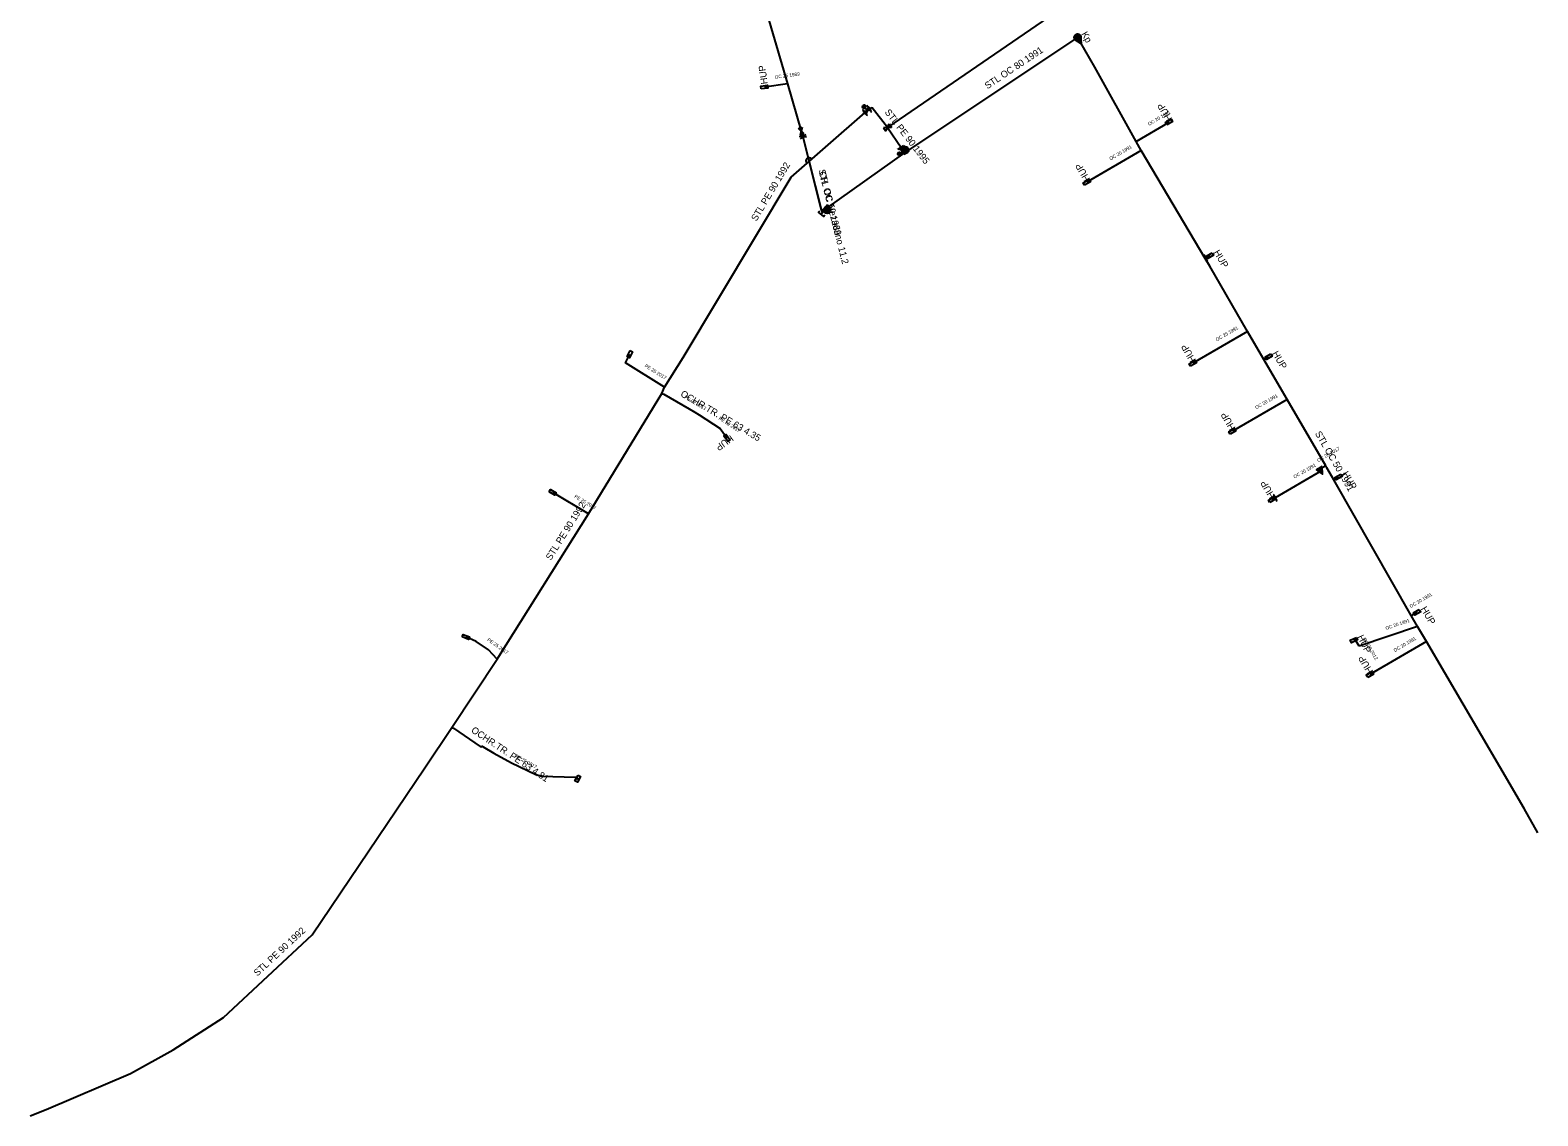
# Model space of a CAD drawing. Extents: x -734239 to -733693, y -1053757 to -1053379.
# Drawn here: x -734167.4 to -733944.2, y -1053757.2 to -1053596.5 of the extents above; entities that cross this region are included whole.
import ezdxf

# ---------------------------------------------------------------- set-up
doc = ezdxf.new("R2010")
doc.units = 0
for name, color, linetype in [('ST Kapák - provoz_popis', 7, 'Continuous'), ('ST Ochoz plynovodu - provoz', 7, 'Continuous'), ('ST OP Chráni_ka - provoz', 7, 'Continuous'), ('ST Úsek p_ípojky - provoz', 7, 'Continuous'), ('ST Úsek p_ípojky - provoz - priblizny prubeh', 7, 'Continuous'), ('ST Úsek plynovodu - provoz', 7, 'Continuous'), ('ST_HUP_22_23_popis', 7, 'Continuous'), ('Vrstva 1', 7, 'Continuous')]:
    doc.layers.add(name, color=color, linetype=linetype)

msp = doc.modelspace()

# ---------------------------------------------------------------- linework, layer by layer
at = {"layer": 'ST Ochoz plynovodu - provoz'}
for points in [[(-734038.21, -1053614.26), (-734037.95, -1053614.08), (-734037.85, -1053614.29), (-734037.65, -1053614.47)], [(-734049.48, -1053622.88), (-734049.33, -1053623.03), (-734049.42, -1053623.17), (-734049.54, -1053623.28), (-734049.71, -1053623.1)]]:
    msp.add_lwpolyline(points, dxfattribs=at)
at = {"layer": 'ST OP Chráni_ka - provoz'}
for points in [[(-734050.22, -1053623.25), (-734052.98, -1053612.39)], [(-734073.59, -1053650.41), (-734069.84, -1053652.61)], [(-734069, -1053653.1), (-734068.33, -1053653.48)], [(-734104.73, -1053699.88), (-734100.74, -1053702.56)], [(-734100.34, -1053702.63), (-734098.72, -1053703.58)], [(-734096.13, -1053705.02), (-734092.52, -1053706.71)], [(-734091.65, -1053706.97), (-734086.72, -1053707.11)]]:
    msp.add_lwpolyline(points, dxfattribs=at)
at = {"layer": 'ST Úsek p_ípojky - provoz'}
for points in [[(-734055.28, -1053604.51), (-734058.7, -1053604.98)], [(-734002.95, -1053614.35), (-734010.96, -1053619.06)], [(-733993.35, -1053630.29), (-733992.74, -1053629.93)], [(-733993.44, -1053630.35), (-733993.35, -1053630.29)], [(-733987.17, -1053641.14), (-733995.29, -1053645.84)], [(-734073.5, -1053649.41), (-734079.25, -1053645.8), (-734078.62, -1053644.5)], [(-733984.76, -1053645.29), (-733984.07, -1053644.89)], [(-734073.9, -1053650.31), (-734073.59, -1053650.41), (-734069.84, -1053652.61), (-734069, -1053653.1), (-734068.33, -1053653.48)], [(-733981.33, -1053651.21), (-733989.43, -1053655.91)], [(-734068.33, -1053653.48), (-734065.26, -1053655.49), (-734064.23, -1053656.92)], [(-733975.62, -1053661.03), (-733976.49, -1053661.53), (-733976.32, -1053661.83)], [(-733976.32, -1053661.83), (-733983.11, -1053665.77)], [(-733974.42, -1053663.1), (-733973.73, -1053662.7)], [(-734084.75, -1053668.12), (-734090.03, -1053664.97)], [(-733983.11, -1053665.77), (-733983.55, -1053666.02)], [(-733962.96, -1053683.21), (-733962.09, -1053682.71)], [(-733962.02, -1053684.82), (-733970.68, -1053687.71)], [(-734098.24, -1053689.67), (-734099.55, -1053688.27), (-734101.34, -1053687.02), (-734102.88, -1053686.36)], [(-733970.68, -1053687.71), (-733971.25, -1053686.74), (-733971.45, -1053686.83)], [(-733960.72, -1053687.04), (-733969.07, -1053691.93)], [(-734104.95, -1053699.77), (-734104.73, -1053699.88), (-734100.74, -1053702.56), (-734100.54, -1053702.65), (-734100.49, -1053702.55), (-734100.34, -1053702.63), (-734098.72, -1053703.58), (-734096.13, -1053705.02), (-734092.52, -1053706.71), (-734091.65, -1053706.97), (-734086.72, -1053707.11), (-734086.31, -1053707.34)]]:
    msp.add_lwpolyline(points, dxfattribs=at)
at = {"layer": 'ST Úsek p_ípojky - provoz - priblizny prubeh'}
msp.add_lwpolyline([(-734003.69, -1053613.01), (-733998.81, -1053610.14)], dxfattribs=at)
at = {"layer": 'ST Úsek plynovodu - provoz'}
for points in [[(-734066.74, -1053498.42), (-734070.16, -1053518.19), (-734070.63, -1053521.47), (-734070.96, -1053536.4), (-734070.88, -1053545.79), (-734069.71, -1053552.02), (-734065.01, -1053571.09), (-734063.82, -1053575.62), (-734059.57, -1053589.99), (-734059.12, -1053591.3), (-734055.28, -1053604.51), (-734053.25, -1053611.48)], [(-733992.91, -1053579.78), (-733994.62, -1053581), (-734014.15, -1053594.44), (-734015.86, -1053594.09), (-734040.47, -1053610.96)], [(-734012.33, -1053597.61), (-734037.92, -1053614.67)], [(-734012.02, -1053598.15), (-734012.33, -1053597.61)], [(-733944.22, -1053715.38), (-733946.26, -1053711.75), (-733949.86, -1053705.6), (-733960.72, -1053687.04), (-733962.02, -1053684.82), (-733962.96, -1053683.21), (-733974.42, -1053663.1), (-733975.45, -1053661.32), (-733975.62, -1053661.03), (-733981.33, -1053651.21), (-733984.76, -1053645.29), (-733987.17, -1053641.14), (-733992.78, -1053631.46), (-733993.44, -1053630.35), (-734002.95, -1053614.35), (-734003.69, -1053613.01), (-734009.77, -1053602.02), (-734012.02, -1053598.15)], [(-734070.74, -1053645.02), (-734054.75, -1053618.31), (-734043.79, -1053608.73)], [(-734043.79, -1053608.73), (-734043.48, -1053608.46)], [(-734043.15, -1053608.21), (-734043.48, -1053608.46)], [(-734040.47, -1053610.96), (-734042.74, -1053608.03), (-734043.15, -1053608.21)], [(-734053.25, -1053611.48), (-734053, -1053612.32), (-734050.22, -1053623.25), (-734050.14, -1053623.61)], [(-734040.47, -1053610.96), (-734038.47, -1053613.9)], [(-734038.47, -1053613.9), (-734038.21, -1053614.26), (-734038.11, -1053614.39)], [(-734038.11, -1053614.39), (-734037.92, -1053614.67)], [(-734037.92, -1053614.67), (-734049.48, -1053622.88), (-734049.59, -1053622.98)], [(-734049.59, -1053622.98), (-734049.71, -1053623.1), (-734050.14, -1053623.61)], [(-734050.14, -1053623.61), (-734050.3, -1053623.79)], [(-734108.93, -1053705.75), (-734104.95, -1053699.77), (-734098.24, -1053689.67), (-734097.98, -1053689.28), (-734084.75, -1053668.12), (-734073.9, -1053650.31), (-734073.5, -1053649.41), (-734070.74, -1053645.02)], [(-734167.37, -1053757.25), (-734164.99, -1053756.32), (-734152.5, -1053750.98), (-734146.2, -1053747.48), (-734138.77, -1053742.67), (-734125.62, -1053730.47), (-734108.93, -1053705.75)]]:
    msp.add_lwpolyline(points, dxfattribs=at)
at = {"layer": 'Vrstva 1'}
for p, q in [((-734044.12, -1053608.36), (-734044.01, -1053608.26)), ((-734044.12, -1053608.36), (-734043.46, -1053609.11)), ((-734044.06, -1053608.57), (-734042.91, -1053608.35)), ((-734043.66, -1053609.02), (-734044.06, -1053608.57)), ((-734043.49, -1053608.46), (-734043.79, -1053608.07)), ((-734043.31, -1053607.91), (-734043.66, -1053609.02)), ((-734043.46, -1053609.11), (-734043.57, -1053609.21)), ((-734043.46, -1053607.81), (-734043.34, -1053607.72)), ((-734042.85, -1053608.61), (-734043.46, -1053607.81)), ((-734042.91, -1053608.35), (-734043.31, -1053607.91)), ((-734042.85, -1053608.61), (-734042.97, -1053608.7)), ((-734053.67, -1053611.08), (-734053.1, -1053610.92)), ((-734052.82, -1053611.88), (-734053.67, -1053611.08)), ((-734052.58, -1053611.99), (-734053.42, -1053612.65)), ((-734053.1, -1053610.92), (-734053.39, -1053612.04)), ((-734053.39, -1053612.04), (-734052.82, -1053611.88)), ((-734039.89, -1053610.93), (-734041.05, -1053611)), ((-734041.05, -1053611), (-734040.71, -1053611.49)), ((-734040.71, -1053611.49), (-734040.23, -1053610.43)), ((-734040.23, -1053610.43), (-734039.89, -1053610.93)), ((-734052.46, -1053612.37), (-734053.54, -1053612.27)), ((-734038.88, -1053614.18), (-734038.97, -1053614.06)), ((-734038.88, -1053614.18), (-734038.06, -1053613.62)), ((-734038.15, -1053613.81), (-734038.64, -1053614.16)), ((-734038.64, -1053614.16), (-734037.58, -1053614.63)), ((-734038.11, -1053614.39), (-734038.52, -1053614.69)), ((-734037.47, -1053614.43), (-734038.22, -1053614.15)), ((-734038.07, -1053614.97), (-734038.15, -1053613.81)), ((-734038.06, -1053613.62), (-734037.97, -1053613.74)), ((-734037.71, -1053613.91), (-734037.98, -1053614.67)), ((-734037.58, -1053614.63), (-734038.07, -1053614.97)), ((-734050.16, -1053623.12), (-734049.02, -1053622.85)), ((-734049.74, -1053623.55), (-734050.16, -1053623.12)), ((-734049.02, -1053623.17), (-734049.82, -1053623.17)), ((-734049.44, -1053622.42), (-734049.74, -1053623.55)), ((-734049.02, -1053622.85), (-734049.44, -1053622.42)), ((-734049.42, -1053622.77), (-734049.42, -1053623.57)), ((-733993.61, -1053629.86), (-733993.48, -1053629.79)), ((-733993.1, -1053630.73), (-733993.61, -1053629.86)), ((-733993.1, -1053630.73), (-733993.23, -1053630.8)), ((-733983.36, -1053665.34), (-733983.24, -1053665.26)), ((-733983.36, -1053665.34), (-733982.86, -1053666.2)), ((-733982.86, -1053666.2), (-733982.99, -1053666.28))]:
    msp.add_line(p, q, dxfattribs=at)
for points in [[(-734011.91, -1053597.34), (-734011.89, -1053597.38), (-734011.87, -1053597.43), (-734011.85, -1053597.47), (-734011.84, -1053597.52), (-734011.84, -1053597.57), (-734011.83, -1053597.62), (-734011.84, -1053597.67), (-734011.84, -1053597.72), (-734011.86, -1053597.77), (-734011.87, -1053597.81), (-734011.9, -1053597.86), (-734011.92, -1053597.9), (-734011.95, -1053597.94), (-734011.99, -1053597.97), (-734012.02, -1053598), (-734012.06, -1053598.03), (-734012.11, -1053598.06), (-734012.15, -1053598.08), (-734012.2, -1053598.09), (-734012.24, -1053598.1), (-734012.29, -1053598.11), (-734012.34, -1053598.11), (-734012.39, -1053598.11), (-734012.44, -1053598.1), (-734012.49, -1053598.09), (-734012.53, -1053598.07), (-734012.58, -1053598.05), (-734012.62, -1053598.02), (-734012.66, -1053597.99), (-734012.69, -1053597.96), (-734012.73, -1053597.92), (-734012.76, -1053597.88), (-734012.78, -1053597.84), (-734012.8, -1053597.8), (-734012.82, -1053597.75), (-734012.83, -1053597.7), (-734012.83, -1053597.65), (-734012.83, -1053597.6), (-734012.83, -1053597.55), (-734012.82, -1053597.51), (-734012.81, -1053597.46), (-734012.79, -1053597.41), (-734012.77, -1053597.37), (-734012.75, -1053597.33), (-734012.72, -1053597.29), (-734012.68, -1053597.25), (-734012.65, -1053597.22), (-734012.61, -1053597.19), (-734012.56, -1053597.17), (-734012.52, -1053597.15), (-734012.47, -1053597.13), (-734012.42, -1053597.12), (-734012.38, -1053597.11), (-734012.33, -1053597.11), (-734012.28, -1053597.11), (-734012.23, -1053597.12), (-734012.18, -1053597.14), (-734012.13, -1053597.15), (-734012.09, -1053597.17), (-734012.05, -1053597.2), (-734012.01, -1053597.23), (-734011.97, -1053597.26), (-734011.94, -1053597.3)], [(-734011.84, -1053597.46), (-734012.7, -1053597.97), (-734011.77, -1053598.58)], [(-734012.52, -1053597.32), (-734012.49, -1053597.3), (-734012.46, -1053597.29), (-734012.43, -1053597.28), (-734012.4, -1053597.27), (-734012.36, -1053597.26), (-734012.33, -1053597.26), (-734012.29, -1053597.26), (-734012.26, -1053597.27), (-734012.23, -1053597.28), (-734012.19, -1053597.29), (-734012.16, -1053597.31), (-734012.13, -1053597.32), (-734012.11, -1053597.34), (-734012.08, -1053597.37), (-734012.06, -1053597.39), (-734012.04, -1053597.42), (-734012.02, -1053597.45), (-734012.01, -1053597.48), (-734012, -1053597.52), (-734011.99, -1053597.55), (-734011.98, -1053597.58), (-734011.98, -1053597.62), (-734011.99, -1053597.65), (-734011.99, -1053597.69), (-734012, -1053597.72), (-734012.01, -1053597.75), (-734012.03, -1053597.78), (-734012.05, -1053597.81), (-734012.07, -1053597.84), (-734012.09, -1053597.86), (-734012.12, -1053597.89), (-734012.14, -1053597.91), (-734012.17, -1053597.92), (-734012.21, -1053597.94), (-734012.24, -1053597.95), (-734012.27, -1053597.96), (-734012.31, -1053597.96), (-734012.34, -1053597.96), (-734012.37, -1053597.96), (-734012.41, -1053597.95), (-734012.44, -1053597.95), (-734012.47, -1053597.93), (-734012.5, -1053597.92), (-734012.53, -1053597.9), (-734012.56, -1053597.88), (-734012.59, -1053597.86), (-734012.61, -1053597.83), (-734012.63, -1053597.8), (-734012.65, -1053597.77), (-734012.66, -1053597.74), (-734012.67, -1053597.71), (-734012.68, -1053597.67), (-734012.68, -1053597.64), (-734012.68, -1053597.61), (-734012.68, -1053597.57), (-734012.68, -1053597.54), (-734012.67, -1053597.5), (-734012.66, -1053597.47), (-734012.64, -1053597.44), (-734012.62, -1053597.41), (-734012.6, -1053597.39), (-734012.58, -1053597.36), (-734012.55, -1053597.34)], [(-734012.17, -1053597.86), (-734012.2, -1053597.88), (-734012.22, -1053597.89), (-734012.25, -1053597.9), (-734012.28, -1053597.91), (-734012.31, -1053597.91), (-734012.34, -1053597.91), (-734012.37, -1053597.91), (-734012.4, -1053597.91), (-734012.43, -1053597.9), (-734012.45, -1053597.89), (-734012.48, -1053597.87), (-734012.51, -1053597.86), (-734012.53, -1053597.84), (-734012.55, -1053597.82), (-734012.57, -1053597.8), (-734012.59, -1053597.77), (-734012.6, -1053597.75), (-734012.61, -1053597.72), (-734012.62, -1053597.69), (-734012.63, -1053597.67), (-734012.63, -1053597.64), (-734012.63, -1053597.61), (-734012.63, -1053597.58), (-734012.63, -1053597.55), (-734012.62, -1053597.52), (-734012.61, -1053597.49), (-734012.6, -1053597.47), (-734012.58, -1053597.44), (-734012.56, -1053597.42), (-734012.54, -1053597.4), (-734012.52, -1053597.38), (-734012.5, -1053597.36), (-734012.47, -1053597.34), (-734012.44, -1053597.33), (-734012.42, -1053597.32), (-734012.39, -1053597.32), (-734012.36, -1053597.31), (-734012.33, -1053597.31), (-734012.3, -1053597.31), (-734012.27, -1053597.32), (-734012.24, -1053597.33), (-734012.21, -1053597.34), (-734012.19, -1053597.35), (-734012.16, -1053597.36), (-734012.14, -1053597.38), (-734012.12, -1053597.4), (-734012.1, -1053597.43), (-734012.08, -1053597.45), (-734012.07, -1053597.47), (-734012.05, -1053597.5), (-734012.05, -1053597.53), (-734012.04, -1053597.56), (-734012.03, -1053597.59), (-734012.03, -1053597.62), (-734012.04, -1053597.65), (-734012.04, -1053597.68), (-734012.05, -1053597.7), (-734012.06, -1053597.73), (-734012.07, -1053597.76), (-734012.09, -1053597.78), (-734012.11, -1053597.81), (-734012.13, -1053597.83), (-734012.15, -1053597.85)], [(-734012.51, -1053597.97), (-734011.88, -1053598.39), (-734011.93, -1053597.63)], [(-734012.25, -1053597.74), (-734012.27, -1053597.75), (-734012.28, -1053597.75), (-734012.29, -1053597.76), (-734012.31, -1053597.76), (-734012.32, -1053597.76), (-734012.34, -1053597.76), (-734012.35, -1053597.76), (-734012.37, -1053597.76), (-734012.38, -1053597.75), (-734012.39, -1053597.75), (-734012.41, -1053597.74), (-734012.42, -1053597.74), (-734012.43, -1053597.73), (-734012.44, -1053597.72), (-734012.45, -1053597.71), (-734012.46, -1053597.69), (-734012.47, -1053597.68), (-734012.47, -1053597.67), (-734012.48, -1053597.65), (-734012.48, -1053597.64), (-734012.48, -1053597.62), (-734012.48, -1053597.61), (-734012.48, -1053597.59), (-734012.48, -1053597.58), (-734012.48, -1053597.57), (-734012.47, -1053597.55), (-734012.47, -1053597.54), (-734012.46, -1053597.53), (-734012.45, -1053597.51), (-734012.44, -1053597.5), (-734012.43, -1053597.49), (-734012.42, -1053597.49), (-734012.4, -1053597.48), (-734012.39, -1053597.47), (-734012.38, -1053597.47), (-734012.36, -1053597.46), (-734012.35, -1053597.46), (-734012.33, -1053597.46), (-734012.32, -1053597.46), (-734012.3, -1053597.46), (-734012.29, -1053597.47), (-734012.27, -1053597.47), (-734012.26, -1053597.48), (-734012.25, -1053597.49), (-734012.24, -1053597.5), (-734012.23, -1053597.51), (-734012.22, -1053597.52), (-734012.21, -1053597.53), (-734012.2, -1053597.54), (-734012.19, -1053597.56), (-734012.19, -1053597.57), (-734012.19, -1053597.58), (-734012.18, -1053597.6), (-734012.18, -1053597.61), (-734012.18, -1053597.63), (-734012.19, -1053597.64), (-734012.19, -1053597.66), (-734012.2, -1053597.67), (-734012.2, -1053597.69), (-734012.21, -1053597.7), (-734012.22, -1053597.71), (-734012.23, -1053597.72), (-734012.24, -1053597.73)], [(-734011.99, -1053598.19), (-734012.02, -1053597.8), (-734012.32, -1053597.98)], [(-734059.17, -1053605.25), (-734059.22, -1053604.85), (-734058.23, -1053604.71), (-734058.18, -1053605.11)], [(-733999.14, -1053610.57), (-733999.34, -1053610.22), (-733998.48, -1053609.71), (-733998.28, -1053610.06)], [(-734011.3, -1053619.48), (-734011.5, -1053619.13), (-734010.63, -1053618.63), (-734010.43, -1053618.98)], [(-733992.41, -1053629.5), (-733992.21, -1053629.85), (-733993.07, -1053630.36), (-733993.27, -1053630.01)], [(-734078.58, -1053643.96), (-734078.22, -1053644.14), (-734078.66, -1053645.04), (-734079.02, -1053644.86)], [(-733995.62, -1053646.27), (-733995.82, -1053645.92), (-733994.96, -1053645.42), (-733994.76, -1053645.77)], [(-733983.73, -1053644.46), (-733983.53, -1053644.81), (-733984.4, -1053645.31), (-733984.6, -1053644.97)], [(-734063.78, -1053657.21), (-734064.1, -1053657.44), (-734064.68, -1053656.63), (-734064.36, -1053656.4)], [(-733989.76, -1053656.33), (-733989.96, -1053655.99), (-733989.1, -1053655.49), (-733988.9, -1053655.83)], [(-733976.14, -1053661.14), (-733977, -1053661.65), (-733976.07, -1053662.26)], [(-733976.81, -1053661.65), (-733976.18, -1053662.07), (-733976.23, -1053661.31)], [(-733976.29, -1053661.87), (-733976.32, -1053661.48), (-733976.62, -1053661.66)], [(-733973.4, -1053662.27), (-733973.2, -1053662.62), (-733974.06, -1053663.13), (-733974.26, -1053662.78)], [(-734090.56, -1053664.89), (-734090.36, -1053664.54), (-734089.5, -1053665.05), (-734089.7, -1053665.4)], [(-733983.88, -1053666.45), (-733984.08, -1053666.1), (-733983.21, -1053665.6), (-733983.01, -1053665.94)], [(-733961.76, -1053682.29), (-733961.56, -1053682.63), (-733962.42, -1053683.14), (-733962.62, -1053682.79)], [(-734103.42, -1053686.35), (-734103.26, -1053685.98), (-734102.34, -1053686.37), (-734102.5, -1053686.74)], [(-733971.08, -1053686.43), (-733970.91, -1053686.8), (-733971.81, -1053687.23), (-733971.99, -1053686.86)], [(-733969.4, -1053692.35), (-733969.61, -1053692.01), (-733968.74, -1053691.5), (-733968.54, -1053691.85)], [(-734086.24, -1053706.81), (-734085.89, -1053707), (-734086.38, -1053707.87), (-734086.73, -1053707.68)]]:
    msp.add_lwpolyline(points, close=True, dxfattribs=at)
msp.add_lwpolyline([(-734049.76, -1053623.93), (-734049.92, -1053624.12), (-734050.68, -1053623.47), (-734050.51, -1053623.28)], dxfattribs=at)
for centre, radius in [((-734043.95, -1053607.87), 0.249), ((-734044.03, -1053607.95), 0.0614), ((-734043.86, -1053607.82), 0.0614), ((-734037.85, -1053614.29), 0.5), ((-734037.85, -1053614.29), 0.4), ((-734038.72, -1053614.83), 0.249), ((-734038.77, -1053614.74), 0.0614), ((-734038.65, -1053614.91), 0.0614), ((-734049.42, -1053623.17), 0.5), ((-734049.42, -1053623.17), 0.4)]:
    msp.add_circle(centre, radius, dxfattribs=at)
msp.add_arc((-734052.04, -1053615.94), 0.5, 41, 221, dxfattribs=at)

# ---------------------------------------------------------------- texts
at = {"layer": 'ST Kapák - provoz_popis'}
msp.add_text('Kp', height=1, rotation=300, dxfattribs=at).set_placement((-734011.83, -1053597.11))
at = {"layer": 'ST OP Chráni_ka - provoz'}
for s, rotation, p in [('CH. OC Nezadáno 11,2', 284.2608, (-734050.63, -1053617.58)), ('OCHR.TR. PE 63 4.35', 329.6013, (-734071.21, -1053650.65)), ('OCHR.TR. PE 63 4.81', 326.1116, (-734102.18, -1053700.39))]:
    msp.add_text(s, height=1, rotation=rotation, dxfattribs=at).set_placement(p)
at = {"layer": 'ST Úsek p_ípojky - provoz'}
for s, rotation, p in [('OC 25 1989', 7.8085, (-734057.13, -1053603.75)), ('OC 20 1991', 30.429, (-734007.46, -1053615.84)), ('OC 25 1991', 30.0983, (-733991.73, -1053642.62)), ('PE 25 2017', 327.8783, (-734076.46, -1053646.37)), ('PE 32 2017', 329.6013, (-734070.6, -1053651.01)), ('OC 20 1991', 30.1218, (-733985.88, -1053652.69)), ('PE 32 2017', 326.7863, (-734065.51, -1053654.13)), ('OC 25 2017', 30.2069, (-733976.71, -1053660.5)), ('OC 20 1991', 30.1221, (-733980.22, -1053662.93)), ('PE 25 2017', 329.1801, (-734086.88, -1053665.69)), ('OC 20 1991', 30.1988, (-733963.03, -1053682.1)), ('OC 20 1991', 18.4627, (-733966.67, -1053685.32)), ('PE 25 2017', 325.0725, (-734099.77, -1053686.89)), ('OC 20 2012', 300.3294, (-733970.16, -1053686.62)), ('OC 20 1991', 30.337, (-733965.4, -1053688.62)), ('PE 25 2017', 330.9266, (-734095.69, -1053704.12))]:
    msp.add_text(s, height=0.5, rotation=rotation, dxfattribs=at).set_placement(p)
at = {"layer": 'ST Úsek p_ípojky - provoz - priblizny prubeh'}
msp.add_text('OC 20 1991', height=0.5, rotation=30.5261, dxfattribs=at).set_placement((-734001.76, -1053610.71))
at = {"layer": 'ST Úsek plynovodu - provoz'}
for s, rotation, p in [('STL OC 80 1991', 33.6911, (-734025.68, -1053605.31)), ('STL PE 90 1995', 307.7326, (-734040.95, -1053608.71)), ('STL PE 90 1992', 59.0969, (-734059.87, -1053624.9)), ('STL OC 50 1989', 284.2704, (-734050.7, -1053617.29)), ('STL OC 50 1991', 300.1279, (-733977.24, -1053656.25)), ('STL PE 90 1992', 57.982, (-734090.29, -1053675.1)), ('STL PE 90 1992', 42.8635, (-734133.74, -1053736.64))]:
    msp.add_text(s, height=1, rotation=rotation, dxfattribs=at).set_placement(p)
at = {"layer": 'ST_HUP_22_23_popis'}
for rotation, p in [(97.81, (-734058.2, -1053604.48)), (120.53, (-733998.31, -1053609.64)), (120, (-734010.46, -1053618.56)), (300.73, (-733992.24, -1053629.43)), (120.1, (-733994.79, -1053645.34)), (300.22, (-733983.57, -1053644.39)), (120, (-733988.93, -1053655.41)), (215.76, (-734063.73, -1053656.42)), (120.16, (-733983.05, -1053665.52)), (300.34, (-733973.23, -1053662.2)), (300.2, (-733961.59, -1053682.21)), (295.51, (-733970.95, -1053686.33)), (120.34, (-733968.57, -1053691.43))]:
    msp.add_text('HUP', height=1, rotation=rotation, dxfattribs=at).set_placement(p)

doc.saveas('drawing.dxf')
